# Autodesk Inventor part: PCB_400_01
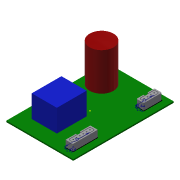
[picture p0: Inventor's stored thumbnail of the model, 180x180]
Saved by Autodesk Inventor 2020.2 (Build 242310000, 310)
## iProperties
Created: 2014-10
Part Number: PCB_400_01
Material: Ogólny
Document SubType Name: Modeling
Designer: F.Stasiak
Density: 1 g/cm^3
Appearance: Domyślna
Catalog Web Link: www.expertbooks.pl
Manager: www.cadconsulting.pl
Company: Fabian Stasiak CAD Consulting
Author: F.Stasiak
Subject: Zbiór ćwiczeń. Autodesk Inventor 2020. Kurs Professional
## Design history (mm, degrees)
sketch "Szkic1"
  geometry: L1 (50, 75)-(-50, 75); L2 (-50, 75)-(-50, -75); L3 (-50, -75)-(50, -75); L4 (50, -75)-(50, 75); L5 (50, 75)-(-50, -75); L6 (-50, 75)-(50, -75); 1 further point
  constraints: 12 end point, 2 midpoint, 2 parallel, 1 horizontal, 1 perpendicular
  dimensions: "d0" = 150 distance of L1.end L2.end; "d1" = 100 distance of L2.end L3.end
extrude "Wyciągnięcie proste1" new body sketch "Szkic1" distance "d2" = 2; taper "d3" = 0 deg
sketch "Szkic2"
  geometry: L1 (-33.098, -53.944)-(4.455, -53.944); L2 (4.455, -53.944)-(4.455, -9.569); L3 (4.455, -9.569)-(-33.098, -9.569); L4 (-33.098, -9.569)-(-33.098, -53.944); 1 further point
  constraints: 8 end point, 2 parallel, 1 horizontal, 1 perpendicular
extrude "Wyciągnięcie proste2" join sketch "Szkic2" distance "d4" = 33.25; taper "d5" = 0 deg
sketch "Szkic3"
  geometry: C1 r 17.832 at (-26.277, 43.614); 1 further point
  constraints: 1 centre point
extrude "Wyciągnięcie proste3" join sketch "Szkic3" distance "d6" = 56.25; taper "d7" = 0 deg
sketch "Szkic5"
  geometry: L1 (30.5, 44.933)-(30.5, 62.933); L2 (36, 42.433)-(33, 42.433); L3 (38.5, 62.933)-(38.5, 44.933); L4 (33, 65.433)-(36, 65.433); L5 (38.5, 62.933)-(38.5, 44.933); L6 (36, 42.433)-(33, 42.433); L7 (30.5, 44.933)-(30.5, 62.933); L8 (33, 65.433)-(36, 65.433); L9 (30.95, 44.933)-(30.95, 62.933); L10 (36, 42.883)-(33, 42.883); L11 (38.05, 62.933)-(38.05, 44.933); L12 (33, 64.983)-(36, 64.983); L13 (29, 50.933)-(29, 56.933); L14 (29, 56.933)-(30.5, 56.933); L15 (30.5, 50.933)-(29, 50.933); L16 (34.5, 65.433)-(34.5, 42.433); L17 (40, 67.433)-(29, 67.433); L18 (29, 67.433)-(29, 40.433); L19 (29, 40.433)-(40, 40.433); L20 (40, 40.433)-(40, 67.433); L21 (40, 67.433)-(29, 40.433); L22 (29, 67.433)-(40, 40.433); L23 (31.35, 44.933)-(31.35, 62.933); L24 (33, 64.583)-(36, 64.583); L25 (37.65, 62.933)-(37.65, 44.933); L26 (36, 43.283)-(33, 43.283); C1 r 1 at (34.5, 61.433); C2 r 1 at (34.5, 56.433); C3 r 1 at (34.5, 51.433); C4 r 1 at (34.5, 46.433); A1 r 2.5 centre (33, 44.933) between (30.5, 44.933) and (33, 42.433); A2 r 2.5 centre (36, 44.933) between (36, 42.433) and (38.5, 44.933); A3 r 2.5 centre (36, 62.933) between (38.5, 62.933) and (36, 65.433); A4 r 2.5 centre (33, 62.933) between (33, 65.433) and (30.5, 62.933); A5 r 2.5 centre (36, 62.933) between (38.5, 62.933) and (36, 65.433); A6 r 2.5 centre (36, 44.933) between (36, 42.433) and (38.5, 44.933); A7 r 2.5 centre (33, 44.933) between (30.5, 44.933) and (33, 42.433); A8 r 2.5 centre (33, 62.933) between (33, 65.433) and (30.5, 62.933); A9 r 2.05 centre (33, 44.933) between (30.95, 44.933) and (33, 42.883); A10 r 2.05 centre (36, 44.933) between (36, 42.883) and (38.05, 44.933); A11 r 2.05 centre (36, 62.933) between (38.05, 62.933) and (36, 64.983); A12 r 2.05 centre (33, 62.933) between (33, 64.983) and (30.95, 62.933); A13 r 1.65 centre (33, 44.933) between (31.35, 44.933) and (33, 43.283); A14 r 1.65 centre (33, 62.933) between (33, 64.583) and (31.35, 62.933); A15 r 1.65 centre (36, 62.933) between (37.65, 62.933) and (36, 64.583); A16 r 1.65 centre (36, 44.933) between (36, 43.283) and (37.65, 44.933); 2 further points
  constraints: 52 end point, 32 point on circle, 20 centre point, 5 midpoint, 2 parallel, 1 horizontal, 1 perpendicular, 7 other
  dimensions: "d13" = 11 distance of L19.end L18.end; "d14" = 27 distance of L18.end L17.end; "d23" = 0.4 radial gap between concentric circles of A9 A13
extrude "Wyciągnięcie proste5" join sketch "Szkic5" distance "d15" = 10; taper "d16" = 0 deg
fillet "Zaokrąglenie1" dims "d17" = 1
extrude "Wyciągnięcie proste7" cut sketch "Szkic5" extent not by distance; stored distance "d24" = 10; taper "d25" = 0 deg
sketch "Szkic6"
  geometry: L1 (38.5, -33)-(38.5, -61); L2 (36, -63.5)-(33, -63.5); L3 (30.5, -61)-(30.5, -33); L4 (33, -30.5)-(36, -30.5); L5 (30.95, -61)-(30.95, -33); L6 (36, -63.05)-(33, -63.05); L7 (38.05, -33)-(38.05, -61); L8 (33, -30.95)-(36, -30.95); L9 (29, -50)-(29, -44); L10 (30.5, -50)-(29, -50); L11 (29, -44)-(30.5, -44); L12 (36, -62.65)-(33, -62.65); L13 (31.35, -61)-(31.35, -33); L14 (33, -31.35)-(36, -31.35); L15 (37.65, -33)-(37.65, -61); L16 (40, -28.5)-(29, -28.5); L17 (29, -28.5)-(29, -65.5); L18 (29, -65.5)-(40, -65.5); L19 (40, -65.5)-(40, -28.5); L20 (40, -28.5)-(29, -65.5); L21 (29, -28.5)-(40, -65.5); C1 r 1 at (34.5, -59.5); C2 r 1 at (34.5, -54.5); C3 r 1 at (34.5, -49.5); C4 r 1 at (34.5, -44.5); C5 r 1 at (34.5, -39.5); C6 r 1 at (34.5, -34.5); A1 r 2.5 centre (36, -33) between (38.5, -33) and (36, -30.5); A2 r 2.5 centre (36, -61) between (36, -63.5) and (38.5, -61); A3 r 2.5 centre (33, -61) between (30.5, -61) and (33, -63.5); A4 r 2.5 centre (33, -33) between (33, -30.5) and (30.5, -33); A5 r 2.05 centre (33, -61) between (30.95, -61) and (33, -63.05); A6 r 2.05 centre (36, -61) between (36, -63.05) and (38.05, -61); A7 r 2.05 centre (36, -33) between (38.05, -33) and (36, -30.95); A8 r 2.05 centre (33, -33) between (33, -30.95) and (30.95, -33); A9 r 1.65 centre (36, -61) between (36, -62.65) and (37.65, -61); A10 r 1.65 centre (33, -61) between (31.35, -61) and (33, -62.65); A11 r 1.65 centre (33, -33) between (33, -31.35) and (31.35, -33); A12 r 1.65 centre (36, -33) between (37.65, -33) and (36, -31.35); 2 further points
  constraints: 42 end point, 24 point on circle, 18 centre point, 2 midpoint, 2 parallel, 1 horizontal, 1 perpendicular, 7 other
  dimensions: "d29" = 0.4 radial gap between concentric circles of A6 A9; "d30" = 11 distance of L18.end L17.end; "d31" = 37 distance of L17.end L16.end
extrude "Wyciągnięcie proste8" join sketch "Szkic6" distance "d32" = 10; taper "d33" = 0 deg
extrude "Wyciągnięcie proste9" join sketch "Szkic6" distance "d34" = 10; taper "d35" = 0 deg
node "Bryła1"
